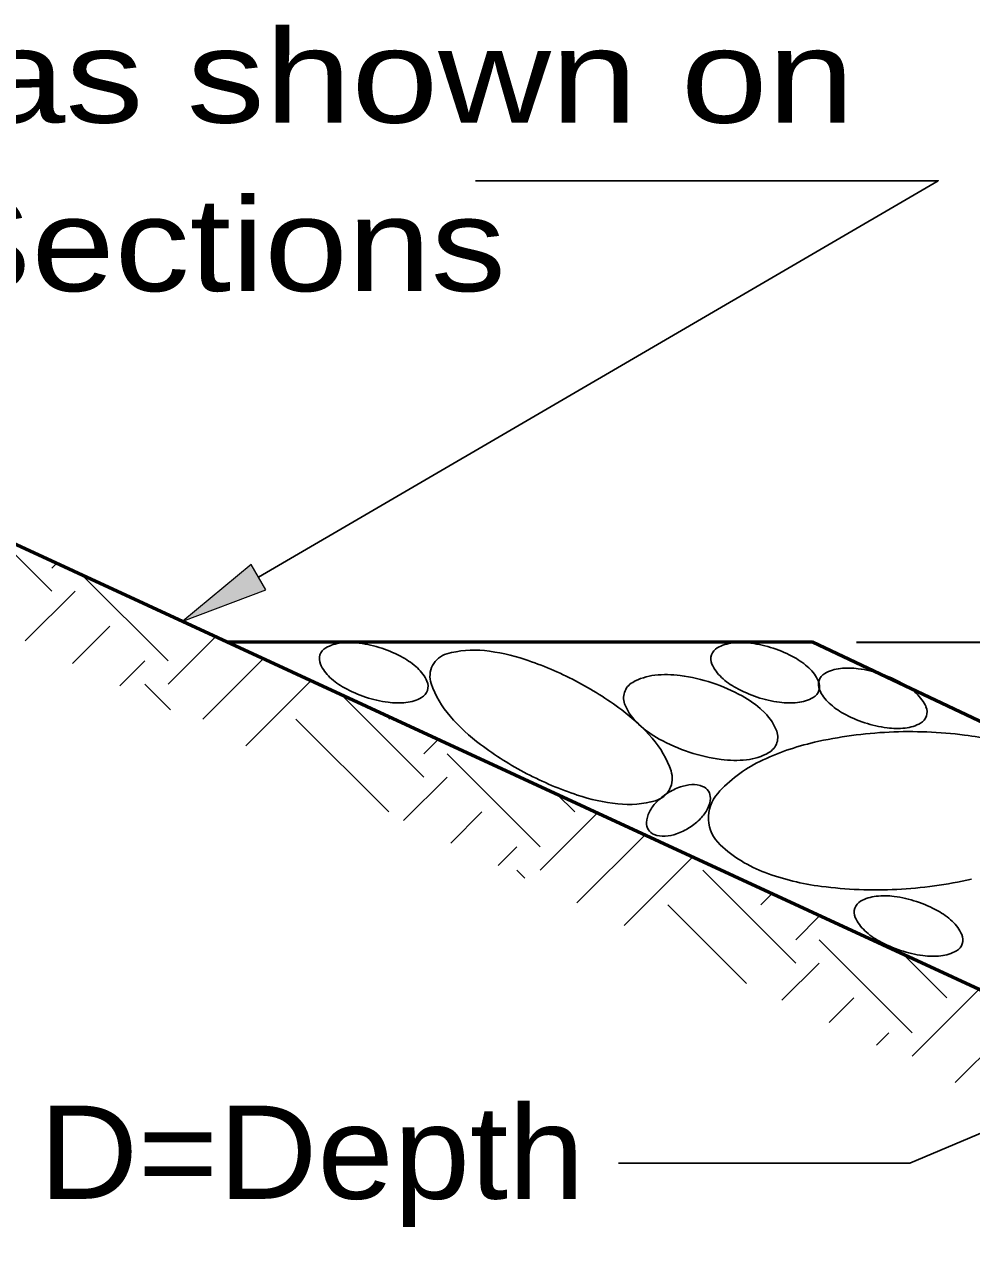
# Model space of a CAD drawing. Extents: x 72.6 to 107.3, y 36.1 to 58.1.
# Drawn here: x 85.556 to 86.906, y 38.097 to 39.845 of the extents above; entities that cross this region are included whole.
import ezdxf

# ---------------------------------------------------------------- set-up
doc = ezdxf.new("R2010")
doc.units = 0
doc.header["$LTSCALE"] = 0.053
for name, color, linetype, lineweight in [('1', 7, 'Continuous', 35), ('3', 7, 'Continuous', 13), ('4', 7, 'Continuous', 25), ('6', 7, 'Continuous', 13)]:
    doc.layers.add(name, color=color, linetype=linetype, lineweight=lineweight)

msp = doc.modelspace()

# ---------------------------------------------------------------- hatches: boundary and pattern name
at = {"layer": '3'}
msp.add_hatch(color=256, dxfattribs=at).paths.add_polyline_path([(85.90008, 39.0385), (85.87908, 39.0745), (85.78158, 38.9935), (85.78158, 38.9935)])
msp.add_hatch(color=256, dxfattribs=at).paths.add_polyline_path([(85.90008, 39.0385), (85.87908, 39.0745), (85.78158, 38.9935), (85.78158, 38.9935)])

# ---------------------------------------------------------------- linework, layer by layer
at = {"layer": '1', "lineweight": 25}
for p, q in [((85.59467, 39.03633), (85.51792, 39.11317)), ((85.59467, 39.03633), (85.51792, 39.11317)), ((85.59467, 39.03633), (85.51792, 39.11317)), ((85.59467, 39.0695), (85.60175, 39.07658)), ((85.59467, 39.0695), (85.60175, 39.07658)), ((85.59467, 39.0695), (85.60175, 39.07658)), ((85.76042, 38.93692), (85.63708, 39.06025)), ((85.76042, 38.93692), (85.63708, 39.06025)), ((85.76042, 38.93692), (85.63708, 39.06025)), ((85.55692, 38.9655), (85.62783, 39.03633)), ((85.55692, 38.9655), (85.62783, 39.03633)), ((85.55692, 38.9655), (85.62783, 39.03633)), ((85.62433, 38.93342), (85.6775, 38.98667)), ((85.62433, 38.93342), (85.6775, 38.98667)), ((85.62433, 38.93342), (85.6775, 38.98667)), ((85.76042, 38.90375), (85.82842, 38.97183)), ((85.76042, 38.90375), (85.82842, 38.97183)), ((85.76042, 38.90375), (85.82842, 38.97183)), ((85.69175, 38.90142), (85.72725, 38.93692)), ((85.69175, 38.90142), (85.72725, 38.93692)), ((85.69175, 38.90142), (85.72725, 38.93692)), ((85.81008, 38.85408), (85.89642, 38.94042)), ((85.81008, 38.85408), (85.89642, 38.94042)), ((85.81008, 38.85408), (85.89642, 38.94042)), ((85.76392, 38.86717), (85.72725, 38.90375)), ((85.76392, 38.86717), (85.72725, 38.90375)), ((85.76392, 38.86717), (85.72725, 38.90375)), ((85.8715, 38.816), (85.96442, 38.909)), ((85.8715, 38.816), (85.96442, 38.909)), ((85.8715, 38.816), (85.96442, 38.909)), ((86.125, 38.77117), (86.00683, 38.88942)), ((86.125, 38.77117), (86.00683, 38.88942)), ((86.125, 38.77117), (86.00683, 38.88942)), ((86.07525, 38.7215), (85.94267, 38.85408)), ((86.07525, 38.7215), (85.94267, 38.85408)), ((86.07525, 38.7215), (85.94267, 38.85408)), ((86.07525, 38.85408), (86.07783, 38.85658)), ((86.07525, 38.85408), (86.07783, 38.85658)), ((86.07525, 38.85408), (86.07783, 38.85658)), ((86.125, 38.80433), (86.14583, 38.82517)), ((86.125, 38.80433), (86.14583, 38.82517)), ((86.125, 38.80433), (86.14583, 38.82517)), ((86.29075, 38.67175), (86.15817, 38.80433)), ((86.29075, 38.67175), (86.15817, 38.80433)), ((86.29075, 38.67175), (86.15817, 38.80433)), ((86.09617, 38.70925), (86.15817, 38.77117)), ((86.09617, 38.70925), (86.15817, 38.77117)), ((86.09617, 38.70925), (86.15817, 38.77117)), ((86.34042, 38.7215), (86.31492, 38.747)), ((86.34042, 38.7215), (86.31492, 38.747)), ((86.34042, 38.7215), (86.31492, 38.747)), ((86.16358, 38.67725), (86.20783, 38.7215)), ((86.16358, 38.67725), (86.20783, 38.7215)), ((86.16358, 38.67725), (86.20783, 38.7215)), ((86.29075, 38.63858), (86.3725, 38.72042)), ((86.29075, 38.63858), (86.3725, 38.72042)), ((86.29075, 38.63858), (86.3725, 38.72042)), ((86.34333, 38.59183), (86.4405, 38.68892)), ((86.34333, 38.59183), (86.4405, 38.68892)), ((86.34333, 38.59183), (86.4405, 38.68892)), ((86.231, 38.64517), (86.25758, 38.67175)), ((86.231, 38.64517), (86.25758, 38.67175)), ((86.231, 38.64517), (86.25758, 38.67175)), ((86.41075, 38.55975), (86.5085, 38.6575)), ((86.41075, 38.55975), (86.5085, 38.6575)), ((86.41075, 38.55975), (86.5085, 38.6575)), ((86.26908, 38.62708), (86.25758, 38.63858)), ((86.26908, 38.62708), (86.25758, 38.63858)), ((86.26908, 38.62708), (86.25758, 38.63858)), ((86.65533, 38.506), (86.52275, 38.63858)), ((86.65533, 38.506), (86.52275, 38.63858)), ((86.65533, 38.506), (86.52275, 38.63858)), ((86.60558, 38.58892), (86.62183, 38.60517)), ((86.60558, 38.58892), (86.62183, 38.60517)), ((86.60558, 38.58892), (86.62183, 38.60517)), ((86.58492, 38.47708), (86.473, 38.58892)), ((86.58492, 38.47708), (86.473, 38.58892)), ((86.58492, 38.47708), (86.473, 38.58892)), ((86.65533, 38.53917), (86.68983, 38.57367)), ((86.65533, 38.53917), (86.68983, 38.57367)), ((86.65533, 38.53917), (86.68983, 38.57367)), ((86.82108, 38.40658), (86.6885, 38.53917)), ((86.82108, 38.40658), (86.6885, 38.53917)), ((86.82108, 38.40658), (86.6885, 38.53917)), ((86.87075, 38.45633), (86.808, 38.51908)), ((86.87075, 38.45633), (86.808, 38.51908)), ((86.87075, 38.45633), (86.808, 38.51908)), ((86.63542, 38.453), (86.6885, 38.506)), ((86.63542, 38.453), (86.6885, 38.506)), ((86.63542, 38.453), (86.6885, 38.506)), ((86.82108, 38.37342), (86.91658, 38.46892)), ((86.82108, 38.37342), (86.91658, 38.46892)), ((86.82108, 38.37342), (86.91658, 38.46892)), ((86.70283, 38.421), (86.73817, 38.45633)), ((86.70283, 38.421), (86.73817, 38.45633)), ((86.70283, 38.421), (86.73817, 38.45633)), ((86.88258, 38.33558), (86.98458, 38.4375)), ((86.88258, 38.33558), (86.98458, 38.4375)), ((86.88258, 38.33558), (86.98458, 38.4375)), ((86.77025, 38.38892), (86.78792, 38.40658)), ((86.77025, 38.38892), (86.78792, 38.40658)), ((86.77025, 38.38892), (86.78792, 38.40658))]:
    msp.add_line(p, q, dxfattribs=at)
at = {"layer": '1'}
msp.add_line((86.74192, 38.96392), (88.17067, 38.96392), dxfattribs=at)
msp.add_line((86.74192, 38.96392), (88.17067, 38.96392), dxfattribs=at)
at = {"layer": '1', "lineweight": 53}
for points in [[(85.51933, 39.11467), (87.7205, 38.09742), (88.70217, 38.09742), (90.43975, 39.0655)], [(85.51933, 39.11467), (87.7205, 38.09742), (88.70217, 38.09742), (90.43975, 39.0655)], [(85.51933, 39.11467), (87.7205, 38.09742), (88.70217, 38.09742), (90.43975, 39.0655)], [(90.13483, 38.89558), (89.39158, 38.89558), (88.63417, 38.52808), (87.59975, 38.52808), (86.67942, 38.96392), (85.8455, 38.96392)], [(90.13483, 38.89558), (89.39158, 38.89558), (88.63417, 38.52808), (87.59975, 38.52808), (86.67942, 38.96392), (85.8455, 38.96392)]]:
    msp.add_lwpolyline(points, dxfattribs=at)
at = {"layer": '3', "lineweight": 25}
for points in [[(85.88958, 39.0565), (86.85858, 39.62192), (86.19883, 39.62192)], [(85.88958, 39.0565), (86.85858, 39.62192), (86.19883, 39.62192)], [(87.87558, 38.6675), (86.81783, 38.2205), (86.4025, 38.2205)], [(87.87558, 38.6675), (86.81783, 38.2205), (86.4025, 38.2205)]]:
    msp.add_lwpolyline(points, dxfattribs=at)
at = {"layer": '3'}
msp.add_lwpolyline([(85.90008, 39.0385), (85.87908, 39.0745), (85.78158, 38.9935), (85.78158, 38.9935)], close=True, dxfattribs=at)
msp.add_lwpolyline([(85.90008, 39.0385), (85.87908, 39.0745), (85.78158, 38.9935), (85.78158, 38.9935)], close=True, dxfattribs=at)
at = {"layer": '4'}
for centre, radius, start, end in [((85.99415, 38.93986), 0.01801, 119.38842, 161.7085), ((86.01386, 38.90493), 0.05813, 96.21788, 119.43731), ((86.01904, 38.85704), 0.10628, 82.40069, 96.19047), ((86.00994, 38.78713), 0.17678, 71.79973, 82.47057), ((86.00968, 38.78724), 0.17676, 61.0352, 71.70604), ((86.1965, 38.81125), 0.14126, 83.86584, 105.88195), ((86.1965, 38.81125), 0.14126, 83.86584, 105.88195), ((86.1815, 38.67442), 0.2789, 71.63396, 83.81593), ((86.1815, 38.67442), 0.2789, 71.63396, 83.81593), ((86.55232, 38.93986), 0.01801, 119.38842, 161.7085), ((86.57203, 38.90493), 0.05813, 96.21788, 119.43731), ((86.57721, 38.85704), 0.10628, 82.40069, 96.19047), ((86.56811, 38.78713), 0.17678, 71.79973, 82.47057), ((86.56785, 38.78724), 0.17676, 61.0352, 71.70604), ((85.99426, 38.9398), 0.01813, 161.58805, 203.90813), ((86.0307, 38.95617), 0.05808, 204.10673, 227.32616), ((86.04398, 38.84904), 0.10607, 47.29394, 61.08373), ((86.16683, 38.91542), 0.03288, 105.85731, 152.43728), ((86.16683, 38.91542), 0.03288, 105.85731, 152.43728), ((86.11625, 38.4785), 0.48538, 62.38313, 71.60529), ((86.11625, 38.4785), 0.48538, 62.38313, 71.60529), ((86.55242, 38.9398), 0.01813, 161.58805, 203.90813), ((86.58887, 38.95617), 0.05808, 204.10673, 227.32616), ((86.60215, 38.84904), 0.10607, 47.29394, 61.08373), ((86.07645, 38.88428), 0.05819, 24.03205, 47.25149), ((86.16683, 38.91533), 0.03298, 152.31131, 198.89128), ((86.16683, 38.91533), 0.03298, 152.31131, 198.89128), ((86.46322, 38.83459), 0.0824, 96.0959, 119.31534), ((86.46322, 38.83459), 0.0824, 96.0959, 119.31534), ((86.47101, 38.76673), 0.15075, 82.51808, 96.30786), ((86.47101, 38.76673), 0.15075, 82.51808, 96.30786), ((86.45744, 38.66757), 0.25085, 71.71093, 82.38176), ((86.45744, 38.66757), 0.25085, 71.71093, 82.38176), ((86.63462, 38.88428), 0.05819, 24.03205, 47.25149), ((86.70557, 38.90336), 0.01801, 119.38842, 161.7085), ((86.72528, 38.86843), 0.05813, 96.21788, 119.43731), ((86.73046, 38.82054), 0.10628, 82.40069, 96.19047), ((86.72136, 38.75063), 0.17678, 71.79973, 82.47057), ((86.7211, 38.75074), 0.17676, 61.0352, 71.70604), ((86.06327, 38.99141), 0.10607, 227.29394, 241.08372), ((86.09763, 39.05347), 0.17702, 241.07167, 251.74251), ((86.1131, 38.90059), 0.01806, 341.82859, 24.14867), ((86.26908, 38.95075), 0.14118, 199.04439, 221.0605), ((86.26908, 38.95075), 0.14118, 199.04439, 221.0605), ((86.11642, 38.47867), 0.48517, 53.17592, 62.39808), ((86.11642, 38.47867), 0.48517, 53.17592, 62.39808), ((86.43548, 38.88414), 0.02562, 119.53439, 161.85447), ((86.43548, 38.88414), 0.02562, 119.53439, 161.85447), ((86.45744, 38.66765), 0.25073, 61.0352, 71.70604), ((86.45744, 38.66765), 0.25073, 61.0352, 71.70604), ((86.62144, 38.99141), 0.10607, 227.29394, 241.08372), ((86.65579, 39.05347), 0.17702, 241.07167, 251.74251), ((86.70567, 38.9033), 0.01813, 161.58805, 203.90813), ((86.67127, 38.90059), 0.01806, 341.82859, 24.14867), ((86.7554, 38.81254), 0.10607, 47.29394, 61.08373), ((86.09763, 39.05326), 0.17684, 251.71093, 262.38176), ((86.09339, 38.93546), 0.05813, 276.21787, 299.43731), ((86.11305, 38.90064), 0.01811, 299.35709, 341.67717), ((86.43548, 38.88406), 0.02561, 161.59907, 203.91914), ((86.43548, 38.88406), 0.02561, 161.59907, 203.91914), ((86.50609, 38.75531), 0.15046, 47.29394, 61.08373), ((86.50609, 38.75531), 0.15046, 47.29394, 61.08373), ((86.65579, 39.05326), 0.17684, 251.71093, 262.38176), ((86.65156, 38.93546), 0.05813, 276.21787, 299.43731), ((86.67122, 38.90064), 0.01811, 299.35709, 341.67717), ((86.74212, 38.91967), 0.05808, 204.10673, 227.32616), ((86.78787, 38.84778), 0.05819, 24.03205, 47.25149), ((86.08821, 38.98315), 0.10606, 262.39924, 276.18902), ((86.24033, 38.64383), 0.27869, 41.02166, 53.20363), ((86.24033, 38.64383), 0.27869, 41.02166, 53.20363), ((86.4874, 38.90728), 0.08253, 204.03205, 227.25149), ((86.4874, 38.90728), 0.08253, 204.03205, 227.25149), ((86.55215, 38.8053), 0.08253, 24.03205, 47.25149), ((86.55215, 38.8053), 0.08253, 24.03205, 47.25149), ((86.64638, 38.98315), 0.10606, 262.39924, 276.18902), ((86.77469, 38.95491), 0.10607, 227.29394, 241.08372), ((86.82452, 38.86409), 0.01806, 341.82859, 24.14867), ((86.37292, 39.04092), 0.27869, 221.02166, 233.20363), ((86.37292, 39.04092), 0.27869, 221.02166, 233.20363), ((86.53346, 38.95756), 0.15071, 227.36266, 241.15244), ((86.53346, 38.95756), 0.15071, 227.36266, 241.15244), ((86.80904, 39.01697), 0.17702, 241.07167, 251.74251), ((86.80904, 39.01676), 0.17684, 251.71093, 262.38176), ((86.80481, 38.89896), 0.05813, 276.21787, 299.43731), ((86.82447, 38.86414), 0.01811, 299.35709, 341.67717), ((86.60414, 38.82844), 0.02561, 341.82859, 24.14867), ((86.60414, 38.82844), 0.02561, 341.82859, 24.14867), ((86.81802, 38.22099), 0.6152, 92.76039, 102.78419), ((86.81802, 38.22099), 0.6152, 92.76039, 102.78419), ((86.81802, 38.22099), 0.6152, 92.76039, 102.78419), ((86.81802, 38.22099), 0.6152, 92.76039, 102.78419), ((86.79963, 38.94665), 0.10606, 262.39924, 276.18902), ((86.8181, 38.22062), 0.61554, 82.73539, 92.75919), ((86.8181, 38.22062), 0.61554, 82.73539, 92.75919), ((86.8181, 38.22062), 0.61554, 82.73539, 92.75919), ((86.8181, 38.22062), 0.61554, 82.73539, 92.75919), ((86.85058, 38.47257), 0.36152, 69.70878, 82.79419), ((86.85058, 38.47257), 0.36152, 69.70878, 82.79419), ((86.85058, 38.47257), 0.36152, 69.70878, 82.79419), ((86.85058, 38.47257), 0.36152, 69.70878, 82.79419), ((86.49683, 39.20608), 0.48517, 233.17592, 242.39808), ((86.49683, 39.20608), 0.48517, 233.17592, 242.39808), ((86.34392, 38.73417), 0.14126, 18.92346, 40.93957), ((86.34392, 38.73417), 0.14126, 18.92346, 40.93957), ((86.58219, 39.04493), 0.25073, 241.0352, 251.70604), ((86.58219, 39.04493), 0.25073, 241.0352, 251.70604), ((86.76202, 38.46842), 0.36149, 102.80576, 115.89117), ((86.76202, 38.46842), 0.36149, 102.80576, 115.89117), ((86.76202, 38.46842), 0.36149, 102.80576, 115.89117), ((86.76202, 38.46842), 0.36149, 102.80576, 115.89117), ((86.60414, 38.82844), 0.02562, 299.53439, 341.85447), ((86.60414, 38.82844), 0.02562, 299.53439, 341.85447), ((86.58219, 39.04501), 0.25085, 251.71093, 262.38176), ((86.58219, 39.04501), 0.25085, 251.71093, 262.38176), ((86.68771, 38.62142), 0.19139, 115.88116, 138.62437), ((86.68771, 38.62142), 0.19139, 115.88116, 138.62437), ((86.68771, 38.62142), 0.19139, 115.88116, 138.62437), ((86.68771, 38.62142), 0.19139, 115.88116, 138.62437), ((86.56884, 38.94555), 0.15045, 262.39924, 276.18902), ((86.56884, 38.94555), 0.15045, 262.39924, 276.18902), ((86.57618, 38.87813), 0.08263, 276.17876, 299.3982), ((86.57618, 38.87813), 0.08263, 276.17876, 299.3982), ((86.497, 39.20625), 0.48538, 242.38313, 251.60529), ((86.497, 39.20625), 0.48538, 242.38313, 251.60529), ((86.44642, 38.76925), 0.03286, 332.48041, 19.06037), ((86.44642, 38.76925), 0.03286, 332.48041, 19.06037), ((86.51026, 38.70226), 0.05838, 93.02881, 109.47763), ((86.50914, 38.72353), 0.03708, 68.73244, 93.05444), ((86.5163, 38.74196), 0.01731, 32.82904, 68.71961), ((86.43167, 39.01), 0.27851, 251.61678, 263.79875), ((86.43167, 39.01), 0.27851, 251.61678, 263.79875), ((86.44633, 38.76933), 0.03303, 285.88367, 332.46364), ((86.44633, 38.76933), 0.03303, 285.88367, 332.46364), ((86.52021, 38.67368), 0.08861, 122.73573, 136.07423), ((86.52035, 38.67371), 0.08867, 109.47631, 122.81482), ((86.4966, 38.743), 0.03705, 332.60197, 356.92397), ((86.51627, 38.74193), 0.01736, 356.96675, 32.85731), ((86.58365, 38.71316), 0.05268, 138.67664, 182.8243), ((86.58365, 38.71316), 0.05268, 138.67664, 182.8243), ((86.58365, 38.71316), 0.05268, 138.67664, 182.8243), ((86.58365, 38.71316), 0.05268, 138.67664, 182.8243), ((86.41692, 38.8735), 0.14124, 263.77764, 285.79375), ((86.41692, 38.8735), 0.14124, 263.77764, 285.79375), ((86.49857, 38.69473), 0.05843, 136.21552, 152.66434), ((86.47758, 38.75286), 0.05849, 316.13726, 332.58607), ((86.45991, 38.70554), 0.01735, 176.82127, 212.71183), ((86.47958, 38.7045), 0.03705, 152.60197, 176.92398), ((86.45583, 38.77368), 0.0886, 302.84584, 316.18434), ((86.58365, 38.71309), 0.05263, 182.76134, 226.90899), ((86.58365, 38.71309), 0.05263, 182.76134, 226.90899), ((86.58365, 38.71309), 0.05263, 182.76134, 226.90899), ((86.58365, 38.71309), 0.05263, 182.76134, 226.90899), ((86.45985, 38.70557), 0.01734, 212.92432, 248.81488), ((86.4671, 38.72395), 0.03709, 248.63072, 272.95272), ((86.46584, 38.74522), 0.0584, 273.12332, 289.57213), ((86.45595, 38.7738), 0.08862, 289.4061, 302.74461), ((86.67844, 38.81433), 0.19129, 226.89173, 249.63493), ((86.67844, 38.81433), 0.19129, 226.89173, 249.63493), ((86.67844, 38.81433), 0.19129, 226.89173, 249.63493), ((86.67844, 38.81433), 0.19129, 226.89173, 249.63493), ((86.73755, 38.97438), 0.36192, 249.67097, 262.75638), ((86.73755, 38.97438), 0.36192, 249.67097, 262.75638), ((86.73755, 38.97438), 0.36192, 249.67097, 262.75638), ((86.73755, 38.97438), 0.36192, 249.67097, 262.75638), ((86.76929, 39.22566), 0.61526, 272.79955, 282.82335), ((86.76929, 39.22566), 0.61526, 272.79955, 282.82335), ((86.76929, 39.22566), 0.61526, 272.79955, 282.82335), ((86.76929, 39.22566), 0.61526, 272.79955, 282.82335), ((86.76974, 39.22551), 0.61512, 262.73383, 272.75763), ((86.76974, 39.22551), 0.61512, 262.73383, 272.75763), ((86.76974, 39.22551), 0.61512, 262.73383, 272.75763), ((86.76974, 39.22551), 0.61512, 262.73383, 272.75763), ((86.77636, 38.5436), 0.05813, 96.21788, 119.43731), ((86.78154, 38.4957), 0.10628, 82.40069, 96.19047), ((86.77244, 38.4258), 0.17678, 71.79973, 82.47057), ((86.75676, 38.57847), 0.01813, 161.58805, 203.90813), ((86.75665, 38.57852), 0.01801, 119.38842, 161.7085), ((86.77218, 38.4259), 0.17676, 61.0352, 71.70604), ((86.7932, 38.59484), 0.05808, 204.10673, 227.32616), ((86.80648, 38.4877), 0.10607, 47.29394, 61.08373), ((86.83895, 38.52294), 0.05819, 24.03205, 47.25149), ((86.82577, 38.63008), 0.10607, 227.29394, 241.08372), ((86.86013, 38.69214), 0.17702, 241.07167, 251.74251), ((86.87555, 38.53931), 0.01811, 299.35709, 341.67717), ((86.8756, 38.53926), 0.01806, 341.82859, 24.14867), ((86.86013, 38.69193), 0.17684, 251.71093, 262.38176), ((86.85071, 38.62181), 0.10606, 262.39924, 276.18902), ((86.85589, 38.57413), 0.05813, 276.21787, 299.43731)]:
    msp.add_arc(centre, radius, start, end, dxfattribs=at)
at = {"layer": '6'}
msp.add_line((86.67942, 38.96392), (86.6795, 38.96392), dxfattribs=at)
msp.add_line((86.67942, 38.96392), (86.6795, 38.96392), dxfattribs=at)

# ---------------------------------------------------------------- texts
at = {"layer": '3'}
for s, width, p in [('Slopes as shown on', 1.25, (84.74908, 39.70475)), ('Slopes as shown on', 1.25, (84.74908, 39.70475)), ('Cross-Sections', 1.2, (84.795, 39.4645)), ('D=Depth', 1.1, (85.5765, 38.16967))]:
    msp.add_text(s, height=0.133, dxfattribs=dict(at, width=width)).set_placement(p)

doc.saveas('drawing.dxf')
